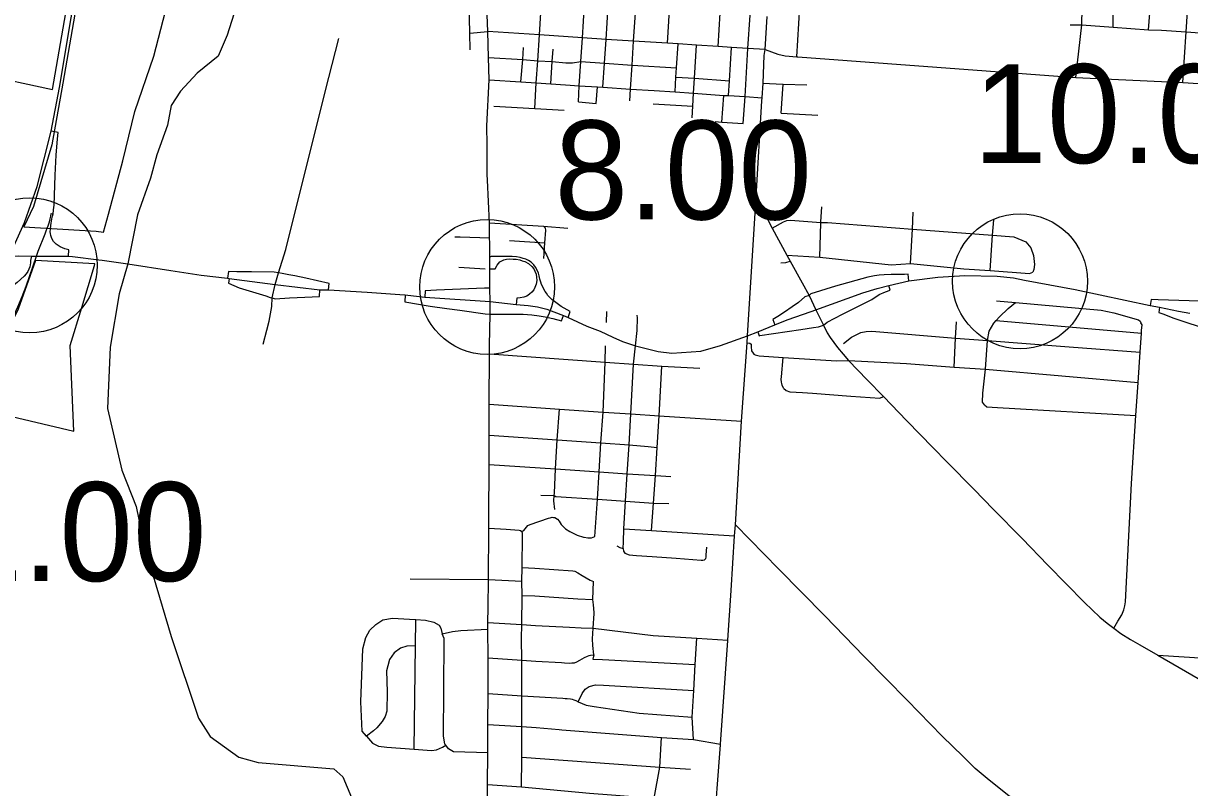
# Model space of a CAD drawing. Extents: x 1729596 to 1934326, y 644115 to 911751.
# Drawn here: x 1824362 to 1837334, y 692845 to 701344 of the extents above; entities that cross this region are included whole.
import ezdxf

# ---------------------------------------------------------------- set-up
doc = ezdxf.new("R2010")
doc.units = 0
for name, color, linetype in [('Default', 7, 'Continuous'), ('GM_X_City_Street', 7, 'Continuous'), ('GM_X_Corporation', 7, 'Continuous'), ('GM_X_County_Road', 7, 'Continuous'), ('GM_X_Interchange_Ramps', 7, 'Continuous'), ('GM_X_Interstate_Route', 7, 'Continuous'), ('GM_X_State_Route', 7, 'Continuous'), ('GM_X_Township', 7, 'Continuous'), ('GM_X_US_Route', 7, 'Continuous')]:
    doc.layers.add(name, color=color, linetype=linetype)

msp = doc.modelspace()

# ---------------------------------------------------------------- linework, layer by layer
at = {"layer": 'Default'}
for centre in [(1824434, 698654), (1835447, 698476), (1829520, 698413)]:
    msp.add_circle(centre, 750, dxfattribs=at)
at = {"layer": 'GM_X_City_Street'}
for points in [[(1830051, 700396), (1830067, 700681), (1830083, 700927), (1830101, 701216), (1830126, 701582), (1830149, 701954), (1830185, 702459), (1830194, 702589), (1830206, 702788), (1830228, 703118), (1830252, 703462), (1830255, 703525), (1830273, 703805), (1830296, 704173), (1830318, 704551), (1830335, 704841), (1830355, 705176), (1830364, 705463), (1830383, 705766)], [(1836066, 700743), (1836134, 701328), (1836146, 701885), (1836146, 701891), (1836184, 702187), (1836207, 702570), (1836267, 703517), (1836306, 704161), (1836360, 705077)], [(1831107, 700481), (1831115, 700612), (1831132, 700880), (1831148, 701146), (1831173, 701514), (1831200, 701886), (1831232, 702383), (1831254, 702716), (1831277, 703044), (1831302, 703389), (1831324, 703733), (1831347, 704103), (1831370, 704486), (1831371, 704499)], [(1829333, 701048), (1829329, 701233), (1829316, 701747), (1829311, 701991), (1829300, 702406), (1829284, 702774), (1829258, 703163), (1829248, 703513), (1829238, 703877)], [(1832089, 701086), (1832111, 701457), (1832135, 701827), (1832145, 701999), (1832163, 702320), (1832184, 702652), (1832205, 702982), (1832226, 703325), (1832246, 703670)], [(1830545, 700650), (1830562, 700918), (1830579, 701183), (1830602, 701553), (1830627, 701924)], [(1830806, 700634), (1830827, 700900), (1830843, 701166), (1830868, 701534), (1830891, 701907)], [(1831526, 701122), (1831550, 701491), (1831569, 701862)], [(1837256, 700687), (1837293, 701249), (1837330, 701819)], [(1832964, 700972), (1833009, 701717)], [(1836481, 701303), (1836487, 701655), (1836490, 701707)], [(1832366, 700231), (1832390, 700529), (1832419, 701066), (1832446, 701435), (1832453, 701549)], [(1836877, 701273), (1836900, 701593)], [(1832513, 699414), (1832575, 700481), (1832579, 700516), (1832589, 700679), (1832603, 700985), (1832612, 701053), (1832634, 701422)], [(1836005, 701328), (1836134, 701328), (1836481, 701303), (1836877, 701273), (1837020, 701267), (1837293, 701249), (1837647, 701224), (1838005, 701203)], [(1827030, 697775), (1827071, 697931), (1827097, 698032), (1827125, 698195), (1827130, 698291), (1827162, 698440), (1827201, 698571), (1827239, 698701), (1827282, 698829), (1827723, 700597), (1827871, 701175)], [(1829329, 701233), (1829527, 701252)], [(1832612, 701053), (1832419, 701066), (1832238, 701077), (1832089, 701086), (1831849, 701101), (1831643, 701115), (1831526, 701122), (1831148, 701146), (1830843, 701166), (1830579, 701183), (1830101, 701216), (1829527, 701252)], [(1829894, 700693), (1829917, 700942), (1829926, 701076)], [(1830229, 700671), (1830245, 700918), (1830255, 701058)], [(1831610, 700581), (1831620, 700744), (1831626, 700848), (1831643, 701115)], [(1831799, 700294), (1831807, 700422), (1831815, 700567), (1831826, 700733), (1831849, 701101)], [(1832205, 700541), (1832216, 700705), (1832238, 701077)], [(1832612, 701053), (1832754, 701001), (1832834, 700984), (1832964, 700972), (1832974, 700971)], [(1829536, 700964), (1829917, 700942), (1830083, 700927), (1830245, 700918), (1830395, 700906), (1830468, 700906), (1830562, 700918), (1830827, 700900), (1831132, 700880), (1831626, 700848)], [(1832974, 700971), (1836066, 700743), (1837256, 700687), (1837606, 700663), (1837971, 700637)], [(1831620, 700744), (1831826, 700733), (1832216, 700705)], [(1829544, 700717), (1829894, 700693), (1830067, 700681), (1830229, 700671), (1830390, 700661), (1830545, 700650), (1830746, 700638), (1830806, 700634), (1831115, 700612), (1831378, 700596), (1831610, 700581), (1831815, 700567), (1832152, 700543), (1832205, 700541), (1832390, 700529), (1832579, 700516)], [(1830536, 700471), (1830545, 700650)], [(1830733, 700453), (1830746, 700638)], [(1832589, 700679), (1832805, 700667)], [(1832790, 700347), (1832811, 700666)], [(1832805, 700667), (1832811, 700666), (1833075, 700659)], [(1832129, 700246), (1832152, 700543)], [(1829595, 700424), (1830051, 700396), (1830378, 700379)], [(1830536, 700471), (1830733, 700453)], [(1831367, 700450), (1831807, 700422)], [(1832055, 700253), (1832129, 700246), (1832366, 700231)], [(1832790, 700347), (1833197, 700323)], [(1832281, 695767), (1832349, 696922), (1832411, 697790), (1832416, 697868), (1832513, 699414)], [(1832513, 699414), (1832593, 699252), (1832691, 699067), (1832854, 698768), (1832890, 698699), (1833024, 698460)], [(1833233, 699136), (1833244, 699304)], [(1834228, 698675), (1834250, 699057), (1834257, 699246)], [(1829546, 699124), (1830148, 699087), (1830416, 699065)], [(1830151, 698728), (1830162, 698904), (1830174, 699043), (1830170, 699065), (1830148, 699087)], [(1832691, 699067), (1832817, 699137), (1832852, 699152), (1832894, 699155), (1833232, 699131), (1833305, 699129), (1834250, 699057), (1835142, 698988), (1835379, 698970), (1835510, 698914), (1835568, 698846), (1835598, 698762), (1835607, 698662), (1835601, 698608), (1835591, 698578)], [(1833221, 698745), (1833232, 699127), (1833232, 699131), (1833233, 699136)], [(1835138, 698932), (1835138, 698932), (1835142, 698988), (1835155, 699158)], [(1829161, 698971), (1829219, 698969), (1829548, 698960)], [(1829769, 698930), (1830162, 698904)], [(1835113, 698594), (1835138, 698932)], [(1832788, 698681), (1832844, 698685), (1832890, 698699)], [(1832854, 698768), (1833221, 698745), (1834015, 698659), (1834228, 698675), (1834822, 698615), (1835113, 698594), (1835553, 698562), (1835591, 698578)], [(1829206, 698632), (1829500, 698615)], [(1833024, 698460), (1833103, 698319), (1833175, 698158), (1833263, 697988), (1833301, 697904), (1833334, 697851), (1833417, 697739), (1833479, 697666), (1833541, 697595)], [(1835050, 697103), (1835028, 697131), (1835033, 697233), (1835064, 697497), (1835085, 697816), (1835085, 697816), (1835105, 697921), (1835157, 698009), (1835182, 698038), (1835218, 698079), (1835316, 698174), (1835396, 698239)], [(1835184, 698258), (1835396, 698239), (1836351, 698155), (1836492, 698126), (1836766, 698046), (1836784, 698034), (1836792, 698012)], [(1830846, 698019), (1830852, 698139)], [(1831148, 697555), (1831172, 697759), (1831188, 697928), (1831192, 698070), (1831187, 698098)], [(1834716, 697522), (1834731, 697844), (1834741, 698026)], [(1835182, 698038), (1836797, 697900)], [(1833483, 697783), (1833571, 697854), (1833677, 697908), (1833734, 697917), (1833798, 697920), (1834731, 697844), (1835085, 697816), (1835992, 697747), (1836783, 697687)], [(1836490, 694618), (1836535, 694696), (1836579, 694767), (1836601, 694821), (1836611, 694866), (1836620, 694911), (1836686, 696226), (1836736, 696982), (1836760, 697352), (1836783, 697687), (1836797, 697900), (1836799, 697930), (1836806, 697992), (1836792, 698012)], [(1832411, 697790), (1832442, 697788), (1832456, 697777), (1832455, 697747), (1832461, 697702), (1832479, 697677), (1832487, 697666), (1832501, 697659), (1832545, 697648), (1832813, 697628), (1833406, 697590), (1833541, 697595)], [(1829546, 697668), (1830834, 697577), (1831148, 697555), (1831462, 697531), (1831884, 697508)], [(1830718, 695639), (1830747, 696052), (1830767, 696356), (1830786, 696679), (1830810, 697022), (1830834, 697577), (1830838, 697757)], [(1831032, 695505), (1831035, 695580), (1831042, 695724), (1831058, 696031), (1831077, 696334), (1831099, 696659), (1831118, 697001), (1831148, 697555)], [(1831349, 695703), (1831371, 696010), (1831394, 696318), (1831412, 696628), (1831434, 696980), (1831462, 697531)], [(1832817, 697289), (1832801, 697322), (1832797, 697338), (1832794, 697353), (1832792, 697386), (1832795, 697413), (1832813, 697628)], [(1833541, 697595), (1834183, 697560), (1834716, 697522), (1835064, 697497), (1836760, 697352)], [(1833541, 697595), (1833748, 697380), (1833928, 697193)], [(1832817, 697289), (1832847, 697260), (1832888, 697248), (1833028, 697238), (1833140, 697230), (1833565, 697199), (1833889, 697177), (1833928, 697193)], [(1833928, 697193), (1834187, 696923), (1834481, 696624), (1834633, 696469), (1834936, 696160), (1835150, 695941), (1835469, 695615), (1835757, 695318), (1835961, 695111), (1836163, 694905), (1836334, 694742), (1836415, 694674), (1836490, 694618), (1836569, 694561), (1836676, 694494), (1836779, 694435), (1836978, 694320), (1837525, 694003)], [(1829544, 697108), (1830326, 697054), (1830810, 697022), (1831118, 697001), (1831434, 696980), (1832349, 696922)], [(1830269, 696119), (1830282, 696390), (1830299, 696711), (1830326, 697054)], [(1835050, 697103), (1835078, 697081), (1835196, 697071), (1836736, 696982)], [(1829543, 696764), (1830299, 696711), (1830786, 696679), (1831099, 696659), (1831311, 696638)], [(1831311, 696638), (1831412, 696628)], [(1829543, 696440), (1830282, 696390), (1830767, 696356), (1831077, 696334), (1831394, 696318), (1831398, 696317)], [(1831398, 696317), (1831562, 696305)], [(1830118, 696098), (1830267, 696095), (1830284, 696084), (1830747, 696052), (1831058, 696031), (1831371, 696010), (1831542, 696004)], [(1830272, 695937), (1830261, 696033), (1830267, 696095), (1830269, 696119)], [(1829540, 695729), (1829733, 695718), (1829875, 695707), (1829892, 695703), (1829905, 695693), (1829930, 695704), (1829973, 695761), (1829998, 695773), (1830202, 695841), (1830221, 695847), (1830243, 695852), (1830257, 695850), (1830272, 695848), (1830302, 695831), (1830321, 695808), (1830344, 695772), (1830393, 695723), (1830441, 695693), (1830521, 695654), (1830592, 695632), (1830600, 695630), (1830640, 695624), (1830680, 695622), (1830718, 695639)], [(1829905, 693538), (1829906, 693866), (1829906, 694262), (1829902, 694504), (1829906, 694658), (1829908, 694980), (1829907, 695141), (1829909, 695292), (1829914, 695650), (1829913, 695674), (1829905, 695693)], [(1831042, 695724), (1831349, 695703), (1831974, 695665), (1832271, 695646)], [(1831848, 689276), (1831878, 689727), (1831916, 690153), (1831941, 690551), (1831966, 690915), (1832006, 691512), (1832068, 692679), (1832080, 692835), (1832116, 693321), (1832116, 693327), (1832197, 694481), (1832197, 694485), (1832233, 695037), (1832271, 695646), (1832281, 695767)], [(1837170, 691164), (1837117, 691253), (1837017, 691383), (1836935, 691468), (1836792, 691587), (1836653, 691694), (1836626, 691715), (1836441, 691861), (1836064, 692164), (1835566, 692562), (1835253, 692811), (1835082, 692948), (1834949, 693059), (1834813, 693190), (1834580, 693419), (1834190, 693818), (1833958, 694057), (1833713, 694305), (1833275, 694755), (1832761, 695277), (1832281, 695767)], [(1830963, 695535), (1830997, 695515), (1831032, 695505)], [(1831032, 695505), (1831037, 695473), (1831050, 695453), (1831101, 695435), (1831180, 695426), (1831355, 695414), (1831623, 695396), (1831900, 695374), (1831920, 695374), (1831939, 695380), (1831952, 695392), (1831957, 695409), (1831958, 695435), (1831964, 695519)], [(1828665, 695167), (1829534, 695160)], [(1829909, 695292), (1830052, 695284), (1830473, 695255), (1830496, 695251), (1830530, 695233), (1830578, 695205), (1830667, 695153), (1830702, 695136)], [(1829534, 695160), (1829907, 695141)], [(1830709, 694781), (1830710, 694793), (1830702, 694879), (1830694, 694936), (1830702, 695136)], [(1829908, 694980), (1830049, 694977), (1830528, 694944), (1830694, 694936)], [(1830708, 694323), (1830696, 694424), (1830693, 694499), (1830700, 694620), (1830709, 694781)], [(1828178, 693417), (1828132, 693475), (1828117, 693800), (1828137, 694387), (1828170, 694514), (1828216, 694596), (1828282, 694658), (1828360, 694711), (1828468, 694729), (1828718, 694716), (1828726, 694715), (1828833, 694706), (1828929, 694685), (1828985, 694651), (1829007, 694617), (1829020, 694555)], [(1828710, 693273), (1828723, 694421), (1828726, 694715)], [(1829527, 694682), (1829906, 694658), (1830058, 694649), (1830436, 694630)], [(1829020, 694555), (1829134, 694582), (1829228, 694594), (1829527, 694607)], [(1829529, 693233), (1829145, 693244), (1829092, 693276), (1829060, 693316), (1829048, 693330), (1829034, 693420), (1829038, 693927), (1829044, 694505), (1829020, 694555)], [(1830436, 694630), (1830567, 694623), (1830700, 694620), (1831368, 694537), (1831851, 694507), (1832197, 694485)], [(1828723, 694421), (1828627, 694419), (1828557, 694395), (1828487, 694344), (1828436, 694270), (1828414, 694200), (1828402, 694144), (1828407, 693909), (1828404, 693697), (1828386, 693638), (1828352, 693580), (1828292, 693512), (1828258, 693478), (1828178, 693417)], [(1831814, 693379), (1831802, 693630), (1831818, 693925), (1831835, 694216), (1831851, 694507)], [(1829530, 694287), (1829906, 694262), (1830063, 694253), (1830346, 694235), (1830379, 694233)], [(1830379, 694233), (1830434, 694229), (1830463, 694232), (1830493, 694234), (1830517, 694243), (1830551, 694263), (1830576, 694277), (1830602, 694292), (1830638, 694308), (1830654, 694313), (1830670, 694318), (1830708, 694323), (1830695, 694274), (1830805, 694272), (1831835, 694216)], [(1836978, 694320), (1837505, 694286)], [(1829530, 693893), (1829906, 693866), (1830363, 693839)], [(1830533, 693801), (1830576, 693892), (1830610, 693941), (1830654, 693971), (1830726, 693987), (1830814, 693985), (1831818, 693925)], [(1830363, 693839), (1830388, 693838), (1830409, 693837), (1830449, 693831), (1830465, 693828), (1830486, 693821), (1830507, 693814), (1830533, 693801), (1830621, 693762), (1830711, 693747), (1831212, 693674), (1831802, 693630)], [(1829527, 693548), (1829905, 693524), (1830064, 693513), (1830321, 693492)], [(1829905, 693170), (1829905, 693185), (1829905, 693524), (1829905, 693538)], [(1830321, 693492), (1830352, 693489), (1831460, 693404), (1831814, 693379), (1832116, 693327)], [(1828178, 693417), (1828247, 693339), (1828311, 693307), (1828403, 693296), (1828710, 693273), (1828902, 693259), (1828958, 693266), (1829022, 693294), (1829060, 693316)], [(1831378, 692730), (1831440, 693073), (1831460, 693404)], [(1829904, 692854), (1829905, 693170)], [(1829905, 693185), (1831440, 693073), (1831781, 693049)], [(1829526, 692880), (1829904, 692854), (1830660, 692783), (1830905, 692765), (1831378, 692730), (1831726, 692704), (1832068, 692679)]]:
    msp.add_lwpolyline(points, dxfattribs=at)
at = {"layer": 'GM_X_Corporation'}
for points in [[(1824368, 699082), (1825173, 699034), (1825253, 699023), (1825308, 699222), (1825467, 699816), (1825602, 700365), (1825812, 700980), (1826020, 701784), (1825023, 701953), (1824993, 701789), (1824800, 700678), (1824677, 699992), (1824474, 699308)], [(1823400, 697168), (1824924, 696809), (1824883, 697761), (1825014, 698186), (1825152, 698652), (1825157, 698669), (1824498, 698707), (1824396, 698427), (1824303, 698165), (1824232, 698012), (1824088, 697858), (1823917, 697692), (1823504, 697292)]]:
    msp.add_lwpolyline(points, close=True, dxfattribs=at)
msp.add_lwpolyline([(1823962, 701679), (1823894, 700779), (1824686, 700610), (1824701, 700695), (1824895, 701807)], dxfattribs=at)
at = {"layer": 'GM_X_County_Road'}
msp.add_lwpolyline([(1824175, 698748), (1824204, 698751), (1824308, 698757), (1824451, 698755), (1824509, 698755)], dxfattribs=at)
at = {"layer": 'GM_X_Interchange_Ramps'}
for points in [[(1824865, 698756), (1824869, 698825), (1824823, 698838), (1824797, 698847), (1824771, 698860), (1824748, 698874), (1824728, 698889), (1824708, 698908), (1824697, 698920), (1824681, 698945), (1824674, 698964), (1824668, 698984), (1824663, 699007), (1824662, 699026), (1824664, 699057), (1824668, 699097), (1824680, 699170), (1824687, 699200), (1824692, 699226), (1824698, 699267), (1824702, 699299), (1824704, 699320), (1824716, 699657), (1824727, 699877), (1824741, 700060), (1824750, 700130), (1824672, 700144)], [(1824509, 698755), (1824527, 698810), (1824603, 699004), (1824616, 699035), (1824627, 699065), (1824637, 699093), (1824644, 699114), (1824651, 699138), (1824660, 699171), (1824666, 699201), (1824672, 699230), (1824692, 699226)], [(1824451, 698755), (1824443, 698706), (1824441, 698682), (1824433, 698636), (1824423, 698610), (1824413, 698584), (1824395, 698557), (1824372, 698533), (1824293, 698464), (1824260, 698435), (1824238, 698408), (1824216, 698376), (1824202, 698341), (1824196, 698312), (1824194, 698269), (1824188, 698181), (1824183, 698107), (1824179, 698076), (1824169, 698042), (1824159, 698024), (1824189, 697996)], [(1830420, 698072), (1830445, 698138), (1830344, 698196), (1830238, 698273), (1830212, 698300), (1830196, 698319), (1830179, 698342), (1830165, 698364), (1830151, 698388), (1830138, 698415), (1830126, 698441), (1830117, 698466), (1830107, 698498), (1830098, 698537), (1830091, 698565), (1830078, 698600), (1830059, 698633), (1830038, 698660), (1830009, 698688), (1829982, 698706), (1829949, 698722), (1829922, 698731), (1829887, 698741), (1829848, 698748), (1829798, 698752), (1829564, 698752), (1829551, 698745)], [(1829551, 698614), (1829609, 698613), (1829631, 698655), (1829660, 698692), (1829684, 698705), (1829707, 698714), (1829736, 698720), (1829772, 698724), (1829810, 698723), (1829844, 698720), (1829882, 698713), (1829910, 698705), (1829941, 698695), (1829979, 698674), (1830018, 698641), (1830038, 698614), (1830052, 698589), (1830065, 698555), (1830071, 698523), (1830072, 698483), (1830066, 698445), (1830052, 698408), (1830038, 698382), (1830018, 698356), (1829992, 698332), (1829962, 698312), (1829927, 698298), (1829887, 698292), (1829849, 698288), (1829842, 698217)], [(1827201, 698571), (1827153, 698579), (1826900, 698580), (1826735, 698581), (1826643, 698584), (1826632, 698510)], [(1827756, 698382), (1827764, 698450), (1827502, 698510), (1827381, 698535), (1827316, 698548), (1827241, 698564), (1827201, 698571)], [(1834212, 698482), (1834204, 698554), (1834162, 698553), (1834012, 698551), (1833935, 698548), (1833882, 698545), (1833827, 698538), (1833756, 698523), (1833393, 698422), (1833119, 698338), (1833103, 698319)], [(1826650, 698506), (1826643, 698454), (1826763, 698403), (1827060, 698313), (1827108, 698297), (1827130, 698291)], [(1833263, 697988), (1833303, 698020), (1833473, 698111), (1833800, 698274), (1833879, 698329), (1833951, 698359), (1834002, 698376), (1833988, 698430)], [(1827130, 698291), (1827163, 698282), (1827321, 698291), (1827491, 698299), (1827654, 698308), (1827661, 698382)], [(1828608, 698324), (1828603, 698247), (1828886, 698200), (1829073, 698173), (1829217, 698154), (1829498, 698114), (1829553, 698110)], [(1829552, 698400), (1829490, 698398), (1828958, 698377), (1828830, 698371), (1828826, 698300)], [(1833103, 698319), (1833054, 698304), (1832983, 698241), (1832914, 698191), (1832828, 698131), (1832754, 698084), (1832697, 698052), (1832721, 697992)], [(1837809, 698250), (1837746, 698251), (1837671, 698247), (1836983, 698269), (1836907, 698274), (1836907, 698274), (1836894, 698208)], [(1836998, 698189), (1836990, 698128), (1837045, 698112), (1837147, 698068), (1837326, 698010), (1837486, 697958), (1837567, 697942), (1837652, 697930), (1837726, 697920), (1837783, 697914)], [(1829553, 698110), (1829584, 698111), (1829922, 698109), (1830016, 698102), (1830098, 698093), (1830167, 698079), (1830251, 698062), (1830348, 698036), (1830369, 698094)], [(1832530, 697914), (1832547, 697871), (1832554, 697873), (1833009, 697940), (1833151, 697961), (1833205, 697969), (1833263, 697988)]]:
    msp.add_lwpolyline(points, dxfattribs=at)
at = {"layer": 'GM_X_Interstate_Route'}
msp.add_lwpolyline([(1824204, 698751), (1824204, 698751), (1824375, 699131), (1824516, 699530), (1824672, 700144), (1824763, 700630), (1825150, 702938), (1825346, 704070), (1825548, 705267)], dxfattribs=at)
at = {"layer": 'GM_X_State_Route'}
for points in [[(1823915, 697749), (1824071, 697873), (1824147, 697945), (1824189, 697996), (1824216, 698031), (1824259, 698102), (1824302, 698192), (1824347, 698307), (1824392, 698420), (1824509, 698755)], [(1824509, 698755), (1824509, 698755), (1824865, 698756), (1824909, 698753), (1825203, 698714), (1825238, 698709)], [(1825238, 698709), (1825525, 698671), (1826002, 698595), (1826341, 698545), (1826632, 698510), (1826650, 698506), (1827162, 698440), (1827661, 698382), (1827756, 698382), (1828187, 698354), (1828551, 698328)], [(1833124, 698141), (1833175, 698158), (1833697, 698346), (1833859, 698394), (1833988, 698430), (1834212, 698482), (1834532, 698523), (1834832, 698541), (1835193, 698533), (1835376, 698513), (1835498, 698487), (1836060, 698386), (1836894, 698208), (1836998, 698189), (1837208, 698145), (1837337, 698123)], [(1828551, 698328), (1828608, 698324), (1828826, 698300), (1829553, 698250)], [(1829553, 698250), (1829842, 698217), (1829975, 698207), (1830079, 698191), (1830183, 698164), (1830369, 698094), (1830420, 698072), (1830629, 697978), (1830776, 697921), (1830920, 697855), (1831027, 697808), (1831172, 697759), (1831422, 697694), (1831573, 697675), (1831896, 697698), (1832114, 697762), (1832416, 697868), (1832530, 697914), (1832721, 697992), (1832858, 698047), (1833124, 698141)]]:
    msp.add_lwpolyline(points, dxfattribs=at)
at = {"layer": 'GM_X_Township'}
msp.add_lwpolyline([(1826730, 701529), (1826629, 701211), (1826527, 700979), (1826296, 700791), (1826108, 700589), (1826007, 700430), (1825964, 700213), (1825848, 699881), (1825776, 699621), (1825631, 699216), (1825525, 698671), (1825429, 698335), (1825328, 697742), (1825299, 697063), (1825458, 696376), (1825617, 695972), (1825704, 695538), (1826007, 694527), (1826311, 693617), (1826441, 693414), (1826759, 693183), (1826975, 693125), (1827814, 693053), (1827915, 692966), (1828059, 692620)], dxfattribs=at)
at = {"layer": 'GM_X_US_Route'}
for points in [[(1829544, 700717), (1829544, 700717), (1829536, 700964), (1829527, 701252), (1829513, 701623), (1829503, 701995), (1829491, 702371), (1829487, 702506), (1829480, 702781), (1829463, 703168), (1829454, 703518), (1829452, 703583), (1829441, 703864), (1829431, 704234), (1829421, 704525), (1829419, 704609), (1829409, 704878), (1829398, 705237), (1829389, 705827), (1829388, 705879)], [(1829519, 699991), (1829517, 700206), (1829544, 700717)], [(1829522, 699679), (1829519, 699991)], [(1829549, 698901), (1829548, 698960), (1829546, 699124), (1829523, 699600), (1829522, 699662), (1829522, 699679)], [(1829553, 698250), (1829552, 698400), (1829552, 698513), (1829551, 698614), (1829551, 698745), (1829549, 698901)], [(1829553, 698110), (1829553, 698250)], [(1829548, 697760), (1829553, 698110)], [(1829166, 689438), (1829323, 689893), (1829459, 690311), (1829490, 690463), (1829511, 690581), (1829524, 690710), (1829530, 690943), (1829526, 692880), (1829529, 693233), (1829527, 693548), (1829530, 693893), (1829530, 694287), (1829527, 694607), (1829527, 694682), (1829530, 694850), (1829534, 695160), (1829540, 695729), (1829539, 695840), (1829543, 696440), (1829543, 696764), (1829544, 697108), (1829546, 697668), (1829548, 697760)]]:
    msp.add_lwpolyline(points, dxfattribs=at)

# ---------------------------------------------------------------- texts
at = {"layer": 'Default'}
for s, p in [('10.00', (1834928, 699790)), ('8.00', (1830270, 699163)), ('12.00', (1822718, 695142))]:
    msp.add_text(s, height=1100, dxfattribs=at).set_placement(p)

doc.saveas('drawing.dxf')
